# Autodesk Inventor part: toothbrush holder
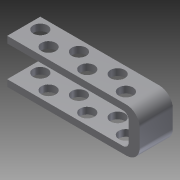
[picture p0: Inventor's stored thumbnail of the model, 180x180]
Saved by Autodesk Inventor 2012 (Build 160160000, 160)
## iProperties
Created: 2012-01
Part Number: toothbrush holder
Material: Default
Document SubType Name: Modeling
Designer: Sam
Density: 1 g/cm^3
Author: Sam
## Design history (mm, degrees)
sketch "Sketch1"
  geometry: L1 (0, 0)-(152.4, 0); L2 (152.4, 0)-(152.4, -50.8); L3 (152.4, -50.8)-(0, -50.8); L4 (0, -50.8)-(0, 0); L5 (0, -7.62)-(139.7, -7.62); L6 (139.7, -7.62)-(139.7, -43.18); L7 (139.7, -43.18)-(0, -43.18); L8 (0, -43.18)-(0, -7.62)
  constraints: 16 end point, 4 parallel, 2 horizontal, 2 perpendicular, 1 point on line
  dimensions: "d0" = 50.8 distance of L1.end L2.end; "d1" = 152.4 distance of L2.end L3.end; "d2" = 7.62 distance between parallel lines of L1 L5; "d3" = 7.62 distance between parallel lines of L7 L3; "d4" = 12.7 distance between parallel lines of L2 L6
extrude "Extrusion1" new body sketch "Sketch1" distance "d5" = 38.1; taper "d6" = 0 deg
sketch "Sketch2" dims "d15" = 25.4, "d25" = 25.4
  geometry: L1 (0, -38.1)-(152.4, -38.1) reference; L2 (152.4, 0)-(0, 0) reference; L3 (0, 0)-(0, -38.1) reference; C1 r 8.255 at (12.7, -12.7); C2 r 8.255 at (57.15, -12.7); C3 r 8.255 at (101.6, -12.7); C4 r 8.255 at (34.925, -25.4); C5 r 8.255 at (79.375, -25.4); C6 r 8.255 at (123.825, -25.4)
  constraints: 6 centre point, 2 horizontal, 8 other
  dimensions: "d7" = 16.51 diameter of C1; "d8" = 12.7 distance from line of L3 C1.centre; "d9" = 12.7 distance from line of L2 C1.centre; "d12" = 44.45 distance of C1.centre C2.centre; "d17" = 16.51 diameter of C4; "d18" = 12.7 distance from line of L1 C4.centre; "d19" = 34.925 distance from line of L3 C4.centre; "d22" = 44.45 distance of C4.centre C5.centre
extrude "Extrusion2" cut sketch "Sketch2" distance "d27" = 50.8; taper "d28" = 0 deg
fillet "Fillet1" dims "d29" = 15.24
fillet "Fillet2" dims "d30" = 6.35
body "Solid1"
